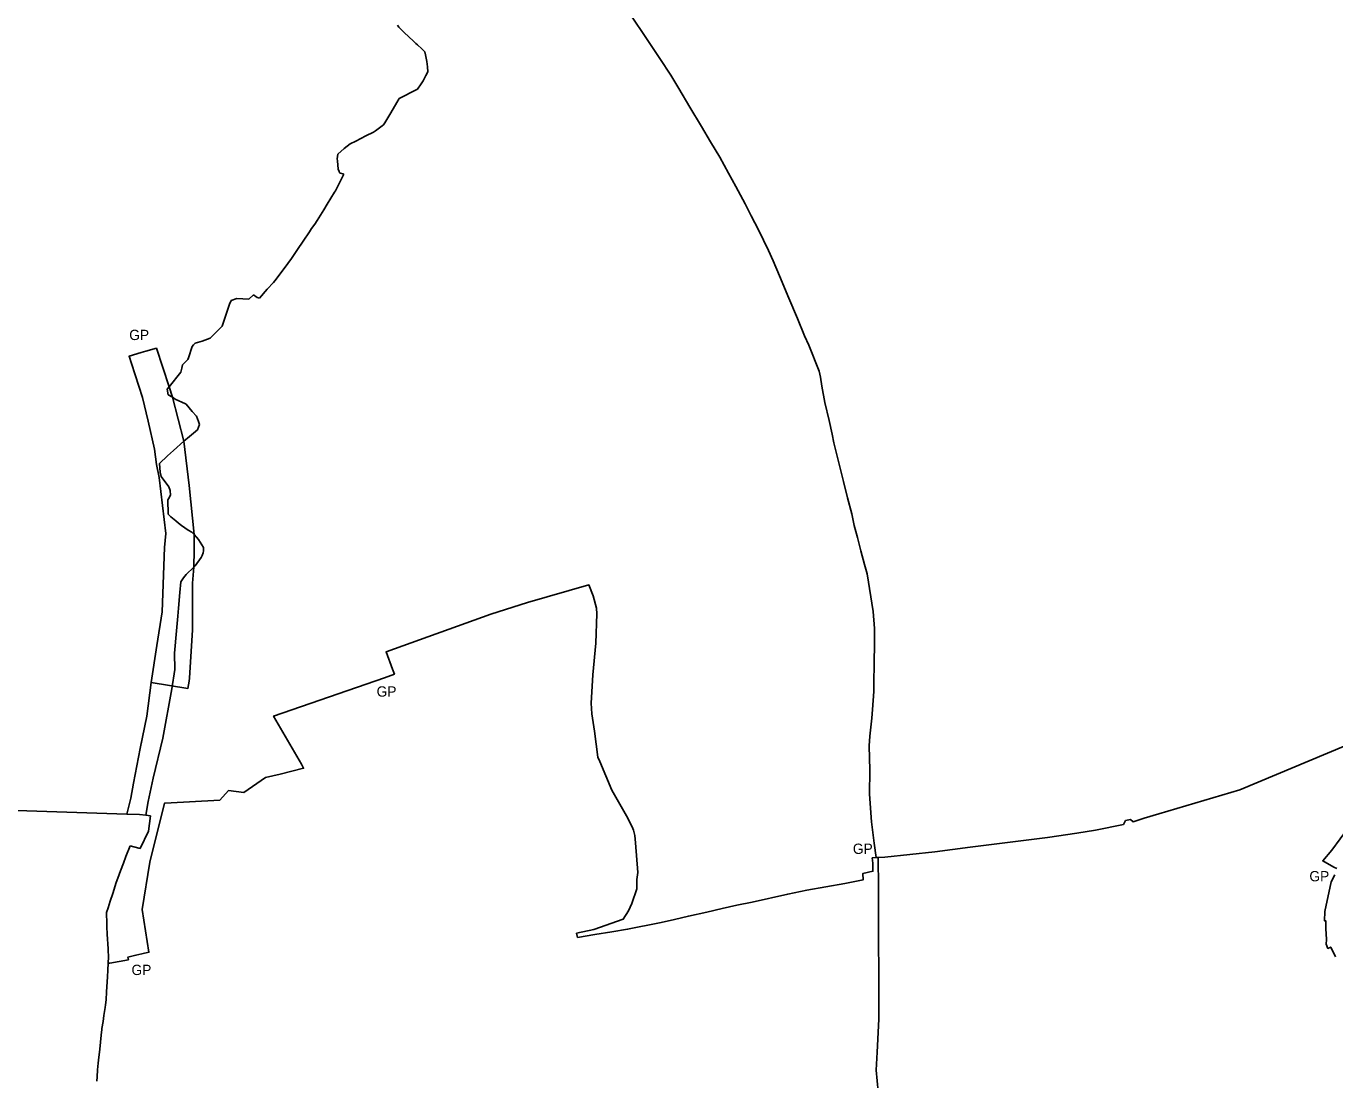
# Model space of a CAD drawing. Extents: x -534397 to -527742, y -1181460 to -1175250.
# Drawn here: x -532132 to -531038, y -1178187 to -1177306 of the extents above; entities that cross this region are included whole.
import ezdxf

# ---------------------------------------------------------------- set-up
doc = ezdxf.new("R2010")
doc.units = 0
doc.layers.add('Hranice parcel', color=7, linetype='Continuous')
doc.layers.add('Hranice státní', color=7, linetype='Continuous')

msp = doc.modelspace()

# ---------------------------------------------------------------- linework, layer by layer
at = {"layer": 'Hranice parcel'}
for p, q in [((-531820.3, -1177307.2), (-531821.4, -1177305.5)), ((-531613.8, -1177315.8), (-531625.8, -1177297.9)), ((-531816.7, -1177310.9), (-531820.3, -1177307.2)), ((-531816, -1177311.6), (-531816.7, -1177310.9)), ((-531812, -1177315.3), (-531816, -1177311.6)), ((-531808.1, -1177319), (-531812, -1177315.3)), ((-531602.1, -1177333.3), (-531613.8, -1177315.8)), ((-531806.2, -1177320.7), (-531808.1, -1177319)), ((-531804.8, -1177322), (-531806.2, -1177320.7)), ((-531801.2, -1177325.4), (-531804.8, -1177322)), ((-531798.7, -1177327.7), (-531801.2, -1177325.4)), ((-531798.1, -1177330.3), (-531798.7, -1177327.7)), ((-531797, -1177335.9), (-531798.1, -1177330.3)), ((-531796.5, -1177340.4), (-531797, -1177335.9)), ((-531593.1, -1177347.2), (-531602.1, -1177333.3)), ((-531800.1, -1177351.9), (-531797.7, -1177347.5)), ((-531797.7, -1177347.5), (-531796.1, -1177344.5)), ((-531796.1, -1177344.5), (-531796.5, -1177340.4)), ((-531586.3, -1177358.4), (-531593.1, -1177347.2)), ((-531820, -1177366.9), (-531805.3, -1177359.2)), ((-531805.3, -1177359.2), (-531804.6, -1177358.9)), ((-531804.6, -1177358.9), (-531801.7, -1177354.4)), ((-531801.7, -1177354.4), (-531800.1, -1177351.9)), ((-531577.2, -1177374), (-531586.3, -1177358.4)), ((-531827.1, -1177378.7), (-531822, -1177370.2)), ((-531822, -1177370.2), (-531820, -1177366.9)), ((-531832.1, -1177387.1), (-531827.1, -1177378.7)), ((-531567.3, -1177390.2), (-531577.2, -1177374)), ((-531839.9, -1177393.8), (-531833.2, -1177388.9)), ((-531833.2, -1177388.9), (-531832.1, -1177387.1)), ((-531559.8, -1177403.1), (-531567.3, -1177390.2)), ((-531861.1, -1177404.7), (-531856.2, -1177402.3)), ((-531856.2, -1177402.3), (-531847.8, -1177398)), ((-531847.8, -1177398), (-531841.5, -1177395)), ((-531841.5, -1177395), (-531839.9, -1177393.8)), ((-531552.1, -1177415.9), (-531559.8, -1177403.1)), ((-531871.9, -1177417.2), (-531871.3, -1177413.3)), ((-531871.3, -1177413.3), (-531865.9, -1177408.7)), ((-531865.9, -1177408.7), (-531861.1, -1177404.7)), ((-531871.7, -1177418.9), (-531871.9, -1177417.2)), ((-531871, -1177425.7), (-531871.7, -1177418.9)), ((-531870.3, -1177427.8), (-531871, -1177425.7)), ((-531544.9, -1177429.2), (-531552.1, -1177415.9)), ((-531873.4, -1177443.9), (-531867.2, -1177431.8)), ((-531869.9, -1177429), (-531870.3, -1177427.8)), ((-531866.3, -1177430), (-531869.9, -1177429)), ((-531867.2, -1177431.8), (-531866.3, -1177430)), ((-531538.7, -1177440.2), (-531544.9, -1177429.2)), ((-531880.2, -1177455.1), (-531874.2, -1177445.1)), ((-531874.2, -1177445.1), (-531873.4, -1177443.9)), ((-531530.9, -1177454.9), (-531538.7, -1177440.2)), ((-531883.1, -1177459.9), (-531880.2, -1177455.1)), ((-531525.7, -1177464.7), (-531530.9, -1177454.9)), ((-531890.6, -1177471.7), (-531888.6, -1177468.8)), ((-531888.6, -1177468.8), (-531883.1, -1177459.9)), ((-531519.6, -1177476.6), (-531525.7, -1177464.7)), ((-531900.3, -1177486.1), (-531894.9, -1177478.2)), ((-531894.9, -1177478.2), (-531893.2, -1177475.5)), ((-531893.2, -1177475.5), (-531890.6, -1177471.7)), ((-531511.4, -1177493.8), (-531519.6, -1177476.6)), ((-531905.1, -1177493), (-531900.3, -1177486.1)), ((-531913.2, -1177504.6), (-531910.1, -1177500.4)), ((-531910.1, -1177500.4), (-531905.1, -1177493)), ((-531507.3, -1177502.4), (-531511.4, -1177493.8)), ((-531502, -1177515), (-531507.3, -1177502.4)), ((-531920.5, -1177514.3), (-531913.2, -1177504.6)), ((-531930.5, -1177526.2), (-531925.1, -1177520.4)), ((-531925.1, -1177520.4), (-531924.1, -1177519.1)), ((-531924.1, -1177519.1), (-531920.5, -1177514.3)), ((-531494.3, -1177533.6), (-531502, -1177515)), ((-531960.4, -1177535.6), (-531955.7, -1177533.8)), ((-531955.7, -1177533.8), (-531945.6, -1177534.3)), ((-531945.6, -1177534.3), (-531941.7, -1177530.9)), ((-531941.7, -1177530.9), (-531938.8, -1177533)), ((-531938.8, -1177533), (-531936.8, -1177533.5)), ((-531936.8, -1177533.5), (-531930.5, -1177526.2)), ((-531487.1, -1177550.5), (-531494.3, -1177533.6)), ((-531964.7, -1177547.1), (-531961.9, -1177538.6)), ((-531961.9, -1177538.6), (-531960.4, -1177535.6)), ((-531978, -1177567), (-531967.9, -1177556.9)), ((-531967.9, -1177556.9), (-531964.7, -1177547.1)), ((-531481.2, -1177565.2), (-531487.1, -1177550.5)), ((-531984.8, -1177569.6), (-531978, -1177567)), ((-531477.5, -1177573), (-531481.2, -1177565.2)), ((-531996.2, -1177583.4), (-531993.2, -1177573.9)), ((-531993.2, -1177573.9), (-531991.9, -1177572.5)), ((-531991.9, -1177572.5), (-531990.6, -1177571.1)), ((-531990.6, -1177571.1), (-531984.8, -1177569.6)), ((-531469, -1177594.5), (-531477.5, -1177573)), ((-532001.8, -1177592.2), (-532001.1, -1177589.2)), ((-532001.1, -1177589.2), (-531996.7, -1177584.8)), ((-531996.7, -1177584.8), (-531996.2, -1177583.4)), ((-532012.4, -1177607.6), (-532002.6, -1177595.4)), ((-532002.6, -1177595.4), (-532001.8, -1177592.2)), ((-531467.9, -1177599.5), (-531469, -1177594.5)), ((-531466.7, -1177607.2), (-531467.9, -1177599.5)), ((-532014, -1177609.5), (-532012.4, -1177607.6)), ((-532013.2, -1177614.4), (-532014, -1177609.5)), ((-531464.1, -1177620.7), (-531466.7, -1177607.2)), ((-532009.6, -1177616.4), (-532013.2, -1177614.4)), ((-532007.2, -1177617.9), (-532009.6, -1177616.4)), ((-531998.7, -1177621.9), (-532007.2, -1177617.9)), ((-531998, -1177622.3), (-531998.7, -1177621.9)), ((-531993, -1177628.2), (-531998, -1177622.3)), ((-531460.6, -1177635.9), (-531464.1, -1177620.7)), ((-531989.5, -1177632.2), (-531993, -1177628.2)), ((-531987.8, -1177636.6), (-531989.5, -1177632.2)), ((-531995.3, -1177649.3), (-531988.6, -1177643.5)), ((-531988.6, -1177643.5), (-531987.1, -1177639.2)), ((-531987.1, -1177639.2), (-531987.8, -1177636.6)), ((-531458.1, -1177647.3), (-531460.6, -1177635.9)), ((-532008.6, -1177661), (-532000.1, -1177653.1)), ((-532000.1, -1177653.1), (-531995.3, -1177649.3)), ((-531456.6, -1177654.4), (-531458.1, -1177647.3)), ((-531453.4, -1177667.9), (-531456.6, -1177654.4)), ((-532020.5, -1177671.6), (-532013.6, -1177665.4)), ((-532013.6, -1177665.4), (-532008.6, -1177661)), ((-532019.8, -1177679.1), (-532020.5, -1177671.6)), ((-531450.9, -1177677.9), (-531453.4, -1177667.9)), ((-532019, -1177682.5), (-532019.8, -1177679.1)), ((-532012.7, -1177691.1), (-532019, -1177682.5)), ((-531448.7, -1177686.8), (-531450.9, -1177677.9)), ((-531445.2, -1177700.4), (-531448.7, -1177686.8)), ((-532013, -1177701.3), (-532011.3, -1177698.1)), ((-532011.6, -1177694.3), (-532012.7, -1177691.1)), ((-532011.3, -1177698.1), (-532011.6, -1177694.3)), ((-532013.3, -1177702), (-532013, -1177701.3)), ((-532013.2, -1177714), (-532013.3, -1177702)), ((-531441.8, -1177713.9), (-531445.2, -1177700.4)), ((-532012.4, -1177714.9), (-532013.2, -1177714)), ((-532011, -1177716.3), (-532012.4, -1177714.9)), ((-532006.7, -1177719.7), (-532011, -1177716.3)), ((-532004.4, -1177721.6), (-532006.7, -1177719.7)), ((-531439.6, -1177723.5), (-531441.8, -1177713.9)), ((-532001.9, -1177723.6), (-532004.4, -1177721.6)), ((-531999.3, -1177725.6), (-532001.9, -1177723.6)), ((-531996.3, -1177727.4), (-531999.3, -1177725.6)), ((-531993.5, -1177729.2), (-531996.3, -1177727.4)), ((-531991.3, -1177731.1), (-531993.5, -1177729.2)), ((-531987.8, -1177735.2), (-531991.3, -1177731.1)), ((-531437, -1177733.5), (-531439.6, -1177723.5)), ((-531983.5, -1177741.8), (-531987.8, -1177735.2)), ((-531983.7, -1177744.8), (-531983.5, -1177741.8)), ((-531434.1, -1177744.6), (-531437, -1177733.5)), ((-531990.6, -1177757.1), (-531985.6, -1177750.3)), ((-531985.6, -1177750.3), (-531984.8, -1177748.6)), ((-531984.8, -1177748.6), (-531983.8, -1177746.5)), ((-531983.8, -1177746.5), (-531983.7, -1177744.8)), ((-531431.2, -1177756.2), (-531434.1, -1177744.6)), ((-532000.3, -1177767.3), (-531998.2, -1177764.5)), ((-531998.2, -1177764.5), (-531991.8, -1177758.3)), ((-531991.8, -1177758.3), (-531990.6, -1177757.1)), ((-531428.9, -1177763.8), (-531431.2, -1177756.2)), ((-531423.9, -1177795.3), (-531428.9, -1177763.8)), ((-532003.5, -1177779.6), (-532002.7, -1177770.5)), ((-532002.7, -1177770.5), (-532000.3, -1177767.3)), ((-532004.4, -1177792.5), (-532003.5, -1177779.6)), ((-532005.1, -1177799.4), (-532004.4, -1177792.5)), ((-531422.6, -1177809.5), (-531423.9, -1177795.3)), ((-532006.3, -1177811.4), (-532005.1, -1177799.4)), ((-532007.8, -1177830.2), (-532006.3, -1177811.4)), ((-531422.6, -1177821.3), (-531422.6, -1177809.5)), ((-532007.7, -1177843.8), (-532007.8, -1177830.2)), ((-531423.1, -1177839.4), (-531422.6, -1177821.3)), ((-531423.3, -1177854.3), (-531423.1, -1177839.4)), ((-532010, -1177859.9), (-532007.7, -1177843.8)), ((-532017.7, -1177901.1), (-532010, -1177859.9)), ((-531424.3, -1177877.2), (-531423.2, -1177862.1)), ((-531423.2, -1177862.1), (-531423.3, -1177854.3)), ((-531426.7, -1177899.6), (-531425, -1177884.5)), ((-531425, -1177884.5), (-531424.3, -1177877.2)), ((-532025.7, -1177934.5), (-532017.7, -1177901.1)), ((-531427.1, -1177907.5), (-531426.7, -1177899.6)), ((-531426.7, -1177927.9), (-531427.1, -1177907.5)), ((-531426.8, -1177948.1), (-531426.7, -1177927.9)), ((-532028.3, -1177946.2), (-532025.7, -1177934.5)), ((-532029.9, -1177954.1), (-532028.3, -1177946.2)), ((-531425.1, -1177971.2), (-531426.8, -1177948.1)), ((-532031.7, -1177965.4), (-532029.9, -1177954.1)), ((-532028, -1177966.2), (-532031.7, -1177965.4)), ((-532029.6, -1177978.9), (-532028, -1177966.2)), ((-531423.1, -1177988.9), (-531425.1, -1177971.2)), ((-532036.6, -1177993.4), (-532029.6, -1177978.9)), ((-532048.6, -1178000.2), (-532044.8, -1177991.1)), ((-532044.8, -1177991.1), (-532037.6, -1177993.1)), ((-532037.6, -1177993.1), (-532036.6, -1177993.4)), ((-531421.4, -1178001), (-531423.1, -1177988.9)), ((-532052.9, -1178012), (-532050.6, -1178005.6)), ((-532050.6, -1178005.6), (-532048.6, -1178000.2)), ((-531421.4, -1178001), (-531421.4, -1178001)), ((-531419.7, -1178001), (-531421.4, -1178001)), ((-531419.7, -1178001), (-531419.7, -1178001)), ((-531419.4, -1178026.1), (-531419.7, -1178001)), ((-532055.2, -1178018.2), (-532052.9, -1178012)), ((-532059.5, -1178031.1), (-532056.6, -1178021.9)), ((-532056.6, -1178021.9), (-532055.2, -1178018.2)), ((-531419.3, -1178049.5), (-531419.4, -1178026.1)), ((-532063.3, -1178042.9), (-532061.5, -1178037.3)), ((-532061.5, -1178037.3), (-532059.5, -1178031.1)), ((-532064.6, -1178046.9), (-532063.3, -1178042.9)), ((-532064.6, -1178048.2), (-532064.6, -1178046.9)), ((-532064.4, -1178054.9), (-532064.6, -1178048.2)), ((-531419.3, -1178072.2), (-531419.3, -1178049.5)), ((-532064.3, -1178059.6), (-532064.4, -1178054.9)), ((-532064.1, -1178064.1), (-532064.3, -1178059.6)), ((-532064.1, -1178065), (-532064.1, -1178064.1)), ((-532063.4, -1178077.2), (-532064.1, -1178065)), ((-532063, -1178085), (-532063.4, -1178077.2)), ((-531419.2, -1178095.5), (-531419.3, -1178072.2)), ((-532063.6, -1178095), (-532063.3, -1178089.3)), ((-532063.3, -1178089.3), (-532063.2, -1178088.1)), ((-532063.2, -1178088.1), (-532063, -1178085)), ((-532064.7, -1178113.1), (-532064, -1178100.6)), ((-532064, -1178100.6), (-532063.6, -1178095)), ((-531419.1, -1178117.6), (-531419.2, -1178095.5)), ((-532065.1, -1178119.9), (-532064.7, -1178113.1)), ((-532066.8, -1178132.8), (-532065.7, -1178126.1)), ((-532065.7, -1178126.1), (-532065.4, -1178123.9)), ((-532065.4, -1178123.9), (-532065.1, -1178119.9)), ((-531419.1, -1178136), (-531419.1, -1178117.6)), ((-532067.6, -1178138), (-532066.8, -1178132.8)), ((-531420.5, -1178163.4), (-531419.1, -1178136)), ((-532069.2, -1178149.3), (-532068.6, -1178144.5)), ((-532068.6, -1178144.5), (-532068.5, -1178143.8)), ((-532068.5, -1178143.8), (-532067.6, -1178138)), ((-532070.4, -1178161.1), (-532069.2, -1178149.3)), ((-532071.4, -1178170.1), (-532070.4, -1178161.1)), ((-531421.2, -1178178.7), (-531420.5, -1178163.4)), ((-532072.6, -1178184.2), (-532072.1, -1178178.2)), ((-532072.1, -1178178.2), (-532071.7, -1178172.8)), ((-532071.7, -1178172.8), (-532071.4, -1178170.1)), ((-531419.6, -1178196.5), (-531421.2, -1178178.7)), ((-532072.8, -1178187.7), (-532072.6, -1178184.2))]:
    msp.add_line(p, q, dxfattribs=at)
for points in [[(-532012.4, -1177607.6), (-532023, -1177575.4), (-532031.7, -1177578), (-532035.7, -1177579.1), (-532045.8, -1177582.1), (-532043.8, -1177588.3), (-532034.7, -1177616.5), (-532030, -1177636.3), (-532024.5, -1177659.8), (-532022.9, -1177672.6), (-532020.6, -1177683.3), (-532015, -1177730.2), (-532016.2, -1177741.9), (-532018.3, -1177795.7), (-532022.6, -1177823.9), (-532027.3, -1177854.6), (-532031.1, -1177882.9), (-532036.2, -1177908.4), (-532036.5, -1177909.9), (-532042, -1177938.7), (-532044.4, -1177951.4), (-532047.7, -1177964.6)], [(-531421.4, -1178001), (-531424.6, -1178001.2), (-531424.1, -1178005.6), (-531424.1, -1178012.4), (-531432.5, -1178014.4), (-531432.3, -1178019.6), (-531447.6, -1178022.5), (-531463.4, -1178025.4), (-531479.4, -1178028.3), (-531495.3, -1178031.4), (-531525, -1178038.2), (-531537.7, -1178040.8), (-531550.1, -1178043.6), (-531563, -1178046.5), (-531578.3, -1178049.9), (-531589.8, -1178052.6), (-531596, -1178054), (-531602.4, -1178055.4), (-531629.1, -1178060.9), (-531642.2, -1178062.9), (-531656.4, -1178065.1), (-531670.9, -1178067.7), (-531671.7, -1178064.2), (-531657.3, -1178061), (-531632.8, -1178052.4), (-531628.3, -1178045.4), (-531625.6, -1178039.4), (-531621.3, -1178027.1), (-531621.3, -1178019.2), (-531620.6, -1178013.4), (-531622.4, -1177988.7), (-531623.1, -1177982.6), (-531624.3, -1177978), (-531625.3, -1177975.4), (-531629.9, -1177966.1), (-531642.3, -1177944.6), (-531652.3, -1177920.8), (-531653.9, -1177917.2), (-531656.9, -1177895.3), (-531658.9, -1177880.9), (-531659.5, -1177872.1), (-531658.3, -1177848.3), (-531655.6, -1177821.8), (-531654.9, -1177797.2), (-531655.1, -1177792.5), (-531657.8, -1177782.2), (-531661.4, -1177773.2), (-531712.8, -1177787.9), (-531743.5, -1177797.6), (-531831, -1177829.1), (-531825.5, -1177843.6), (-531824, -1177847.7), (-531832.4, -1177850.9), (-531925, -1177882.8), (-531901.7, -1177922.9), (-531900, -1177926.4), (-531919.5, -1177931.2), (-531931.9, -1177934.2), (-531949.9, -1177946.7), (-531962.7, -1177944.8), (-531970, -1177952.9), (-532015.7, -1177955.6), (-532016.3, -1177955.6), (-532028.4, -1178004.8), (-532034.9, -1178044.4), (-532029.3, -1178080), (-532035.2, -1178081.4), (-532040.1, -1178082.6), (-532046.9, -1178084.2), (-532046.4, -1178086.3), (-532062, -1178089.1), (-532063.3, -1178089.3)], [(-531028.6, -1177907.2), (-531117.4, -1177944.3), (-531185, -1177964.4), (-531197.4, -1177968.1), (-531206.4, -1177971.1), (-531208.7, -1177969.1), (-531212.9, -1177970.1), (-531214.6, -1177973.2), (-531238, -1177978.1), (-531253.6, -1177980.6), (-531278.1, -1177984.3), (-531342.7, -1177992.4), (-531372.3, -1177996.1), (-531414.2, -1178000.5), (-531419.7, -1178001)], [(-532047.7, -1177964.6), (-532037.1, -1177965.1), (-532031.7, -1177965.4)], [(-531036.3, -1178010.2), (-531038.8, -1178008.9), (-531048, -1178003.7), (-531040.5, -1177994.8), (-531026.6, -1177975.7)], [(-531037.3, -1178084), (-531041.4, -1178075.8), (-531043.7, -1178076.8), (-531045.1, -1178073.4), (-531044.8, -1178069.5), (-531045.4, -1178060.3), (-531045.4, -1178053.9), (-531046.5, -1178053.9), (-531046.4, -1178045.9), (-531040.9, -1178021.2), (-531037.8, -1178015.3)]]:
    msp.add_lwpolyline(points, dxfattribs=at)
at = {"layer": 'Hranice státní'}
msp.add_line((-532047.7, -1177964.6), (-533549.7, -1177914.9), dxfattribs=at)
msp.add_lwpolyline([(-532047.7, -1177964.6), (-532044.4, -1177951.4), (-532042, -1177938.7), (-532036.5, -1177909.9), (-532031.1, -1177882.9), (-532027.3, -1177854.6), (-531996.6, -1177859.7), (-531995.7, -1177853.7), (-531995.3, -1177851.1), (-531992.9, -1177810.8), (-531992.9, -1177802.9), (-531992.8, -1177781.6), (-531992.7, -1177771.7), (-531991.8, -1177758.3), (-531991.5, -1177744.1), (-531991.3, -1177731.1), (-531995.6, -1177690.1), (-532000.1, -1177653.1), (-532009.6, -1177616.4), (-532012.4, -1177607.6)], dxfattribs=at)

# ---------------------------------------------------------------- texts
at = {"layer": 'Hranice parcel'}
for p in [(-532045.7, -1177568.6), (-531838.9, -1177866.5), (-531440.8, -1177997.9), (-531059.2, -1178020.8), (-532043.8, -1178099.1)]:
    msp.add_text('GP', height=8.59, dxfattribs=at).set_placement(p)

doc.saveas('drawing.dxf')
